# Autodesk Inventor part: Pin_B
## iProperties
Shininess: 0.0
Length Units: 11272
Angle Units: 11279
Time Units: 11290
Mass Units: 11283
Length Display Precision: 3
Angle Display Precision: 1
Created: 1999-07
Part Number: Pin_B
Document SubType Name: Modeling
Designer: Administrator
Density: 1 g/cm^3
Density: 0.0
Volumn: 0.0
Area: 0.0
PropertySet Name: Model Information
Control State: 0
Master: False
Checked Out: False
Author: Administrator
